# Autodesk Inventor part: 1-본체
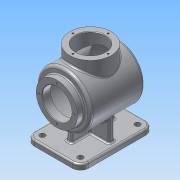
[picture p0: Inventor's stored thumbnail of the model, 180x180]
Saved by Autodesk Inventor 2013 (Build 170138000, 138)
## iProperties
Created: 2016-09
Part Number: 1-본체
Material: 알루미늄 6061
Document SubType Name: Modeling
Designer: Administrator
Density: 2.71 g/cm^3
Mass: 971.049 g
Surface Area: 1286.63 cm^2
Volume: 358.321 cm^3
Author: Administrator
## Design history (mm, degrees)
sketch "스케치1"
  geometry: L1 (-67.5, 50)-(67.5, 50); L2 (67.5, 50)-(67.5, -50); L3 (67.5, -50)-(-67.5, -50); L4 (-67.5, -50)-(-67.5, 50); 3 further points
  constraints: 8 end point, 2 midpoint, 2 parallel, 1 horizontal, 1 horizontal alignment, 1 perpendicular, 1 vertical alignment
  dimensions: "d0" = 135 distance of L1.start L1.end; "d2" = 100 distance of L1.end L2.end
extrude "돌출1" new body sketch "스케치1" distance "d3" = 10; taper "d4" = 0 deg
fillet "모깎기1" dims "d5" = 15
fillet "모깎기2" dims "d6" = 3
sketch "스케치2"
  geometry: C1 r 5 at (-52.5, 35); C2 r 5 at (-52.5, -35); C3 r 5 at (52.5, -35); C4 r 5 at (52.5, 35); A1 r 12 centre (52.5, -35) between (52.5, -47) and (64.5, -35) reference; A2 r 12 centre (52.5, 35) between (64.5, 35) and (52.5, 47) reference; A3 r 12 centre (-52.5, 35) between (-52.5, 47) and (-64.5, 35) reference; A4 r 12 centre (-52.5, -35) between (-64.5, -35) and (-52.5, -47) reference; 1 further point
  constraints: 4 centre point, 4 coincident, 3 equal radius
  dimensions: "d7" = 10 diameter of C1
extrude "돌출2" cut sketch "스케치2" distance "d9" = 10; taper "d10" = 0 deg
sketch "스케치3"
  geometry: L1 (-61, 82)-(61, 82); L2 (-52.5, 0)-(52.5, 0) reference; L3 (-61, 120)-(-49, 120); L4 (-49, 120)-(-49, 132); L5 (-49, 132)-(49.562, 132); L6 (-61, 120)-(-61, 109); L7 (-61, 109)-(-46, 109); L8 (-46, 109)-(-46, 129); L9 (-46, 129)-(47.661, 129); A1 r 115 centre (-54, 82) between (61, 82) and (49.562, 132); A2 r 112 centre (-54, 82) between (58, 82) and (47.661, 129); 2 further points
  constraints: 16 end point, 4 parallel, 4 point on circle, 3 perpendicular, 3 point on line, 2 centre point, 2 vertical alignment, 1 horizontal, 1 midpoint
  dimensions: "d11" = 82 distance between parallel lines of L2 L1; "d14" = 76 diameter of L3 L1; "d15" = 100 diameter of L5 L1; "d17" = 115 radius of A1; "d18" = 112 radius of A2; "d20" = 94 diameter of L9 L1; "d21" = 3 distance of A2.start L1.end; "d22" = 54 diameter of L7 L1; "d23" = 15 distance of L6.end L7.end; "d105" = 110 distance from line of L4 L1.end; "d106" = 122 distance from line of L6 L1.end
revolve "회전1" sketch "스케치3" stored, may be unused: angle "d24" = 90 deg
node "작업 평면1"
sketch "스케치4"
  geometry: L1 (52.5, 50)-(-52.5, 50) reference; L2 (49, 50)-(49, -50) reference; C1 r 38 at (-1, 0); 1 further point
  constraints: 1 centre point, 1 horizontal alignment
  dimensions: "d82" = 76 diameter of C1; "d84" = 50 distance from line of L2 C1.centre
extrude "돌출3" join sketch "스케치4" stored distance "d28" = 10; taper "d29" = 0 deg
fillet "모깎기3" dims "d34" = 2
fillet "모깎기4" dims "d35" = 5
fillet "모깎기5" dims "d36" = 5
chamfer "모따기1" distance "d37" = 1; stored, may be unused: second distance "d38" = 2, angle "d39" = 45 deg
sketch "스케치7" dims "d52" = 65
  geometry: C1 r 38 at (0, 0) reference; C2 r 28 at (0, 0) reference; 3 further points
  constraints: 2 vertical alignment, 1 coincident, 2 other
hole "구멍2" sketch "스케치7" at (0, 32.5) diameter "d54" = 3.242; stored, may be unused: countersink angle "d58" = 90 deg, drill point angle "d60" = 118 deg; dims "d55" = 8, "d56" = 4, "d57" = 2, "d59" = 10
sketch "스케치8"
  geometry: L1 (-35, 10)-(35, 10) reference; L2 (-47, 10)-(-35, 10) reference; L3 (35, 10)-(47, 10) reference; L4 (-40, 10)-(-40, 52); L5 (40, 10)-(40, 52); A1 r 50 centre (0, 82) between (-40, 52) and (40, 52) reference; 1 further point
  constraints: 4 end point, 2 point on circle, 2 point on line, 1 parallel, 1 perpendicular
  dimensions: "d65" = 40 distance from line of A1.centre L4; "d66" = 40 distance from line of A1.centre L5
extrude "돌출5" join sketch "스케치8" stored distance "d67" = 10; taper "d68" = 0 deg
sketch "스케치9"
  geometry: L1 (-52.5, 10)-(52.5, 10) reference; L2 (52.5, 10)-(64.5, 10) reference; L3 (41, 10)-(38.864, 34.41); L4 (-37, 147)-(39, 147) reference; 2 further points
  constraints: 2 end point, 1 midpoint, 1 point on line
  dimensions: "d69" = 95 deg angle of L3 L1; "d108" = 40 horizontal distance of L3.start point (1, 147)
fillet "모깎기7" dims "d77" = 3
fillet "모깎기8" dims "d78" = 3
node "작업 평면3"
sketch "스케치10"
  geometry: C1 r 47.045 at (0, 82) reference; 2 further points
  constraints: 1 coincident, 1 other
feature "엠보싱1" sketch "스케치10" dims "d0" = 135, "d2" = 100, "d80" = 0.5, "d81" = 0
sketch "스케치11"
  geometry: C1 r 38 at (0, 0) reference; C2 r 27 at (0, 0); 1 further point
  constraints: 1 centre point, 1 coincident
  dimensions: "d85" = 54 diameter of C2
extrude "돌출6" cut sketch "스케치11" stored distance "d87" = 10; taper "d88" = 0 deg
sketch "스케치12" dims "d89" = 65
  geometry: C1 r 27 at (0, 0) reference; C2 r 38 at (0, 0) reference; 3 further points
  constraints: 2 vertical alignment, 1 coincident, 2 other
hole "구멍3" sketch "스케치12" at (0, 32.5) diameter "d91" = 3.242; stored, may be unused: countersink angle "d95" = 90 deg, drill point angle "d97" = 118 deg; dims "d92" = 8, "d93" = 4, "d94" = 2, "d96" = 10
fillet "모깎기9" dims "d101" = 3
chamfer "모따기2" distance "d102" = 1; stored, may be unused: second distance "d103" = 2, angle "d104" = 45 deg
fillet "모깎기10" dims "d107" = 2
feature "리브2" dims "d110" = 1, "d111" = 10, "d112" = 0, "d113" = 0, "d114" = 1, "d115" = 1
sketch "스케치13"
  geometry: L1 (-57.5, 10)-(-47.5, 10) reference; L2 (-52.5, 10)-(52.5, 10) reference; L3 (-64.5, 10)-(-52.5, 10) reference; L4 (-39, 10)-(-36.879, 34.244); L5 (29, 147)-(-27, 147) reference; L6 (-26, 146)-(28, 146) reference; 2 further points
  constraints: 2 end point, 1 midpoint, 1 point on line
  dimensions: "d116" = 95 deg angle of L4 L2; "d117" = 40 horizontal distance of L4.start point (1, 146)
feature "리브3" sketch "스케치13" dims "d119" = 1, "d120" = 10, "d121" = 0, "d122" = 0, "d123" = 1, "d124" = 1
fillet "모깎기11" dims "d125" = 3
node "솔리드1"
pattern_circular "원형 패턴2" dims angle "d62" = 360 deg
pattern_circular "원형 패턴3" dims angle "d99" = 360 deg
node "투영된 루프1"
other parameters: "d25" = 147
